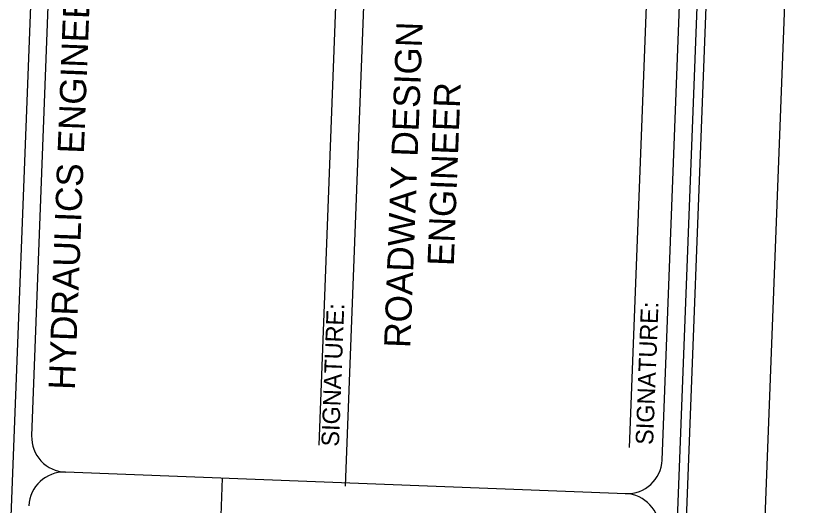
# Model space of a CAD drawing. Extents: x 2094564 to 2100382, y 679033 to 692366.
# Drawn here: x 2099233 to 2100382, y 688399 to 689098 of the extents above; entities that cross this region are included whole.
import ezdxf

# ---------------------------------------------------------------- set-up
doc = ezdxf.new("R2010")
doc.units = 0
for name, color, linetype in [('Prop Horizontal Alignment Direction Label', 7, 'Continuous'), ('Prop Horizontal Alignment Tick Label', 7, 'Continuous'), ('Prop Horizontal Alignment Tick Large', 7, 'Continuous')]:
    doc.layers.add(name, color=color, linetype=linetype)

msp = doc.modelspace()

# ---------------------------------------------------------------- linework, layer by layer
at = {"layer": 'Prop Horizontal Alignment Direction Label'}
for p, q in [((2099030, 683278.9), (2099302.1, 690373.6)), ((2099702.7, 688427.4), (2099745, 689529.9)), ((2099255.2, 688499.1), (2099293.5, 689497.2)), ((2099665, 688485.8), (2099692.6, 689206.5)), ((2100108, 688482.6), (2100135.1, 689189.6)), ((2100102.7, 688416.5), (2099303.3, 688447.2)), ((2099526.9, 688438.6), (2099468.4, 686914.7))]:
    msp.add_line(p, q, dxfattribs=at)
for points in [[(2099968.8, 682967.7), (2100252.4, 690362.2)], [(2100154.6, 688464.6), (2100192.8, 689462.7)]]:
    msp.add_lwpolyline(points, dxfattribs=at)
for centre, start, end in [((2099305, 688497.2), 177.8037, 267.8037), ((2100104.4, 688466.5), 267.8037, 357.8037), ((2099301.1, 688397.3), 87.8037, 177.8037), ((2100100.5, 688366.6), 357.8037, 87.8037)]:
    msp.add_arc(centre, 50, start, end, dxfattribs=at)
at = {"layer": 'Prop Horizontal Alignment Tick Label'}
msp.add_lwpolyline([(2099950.1, 682147.8), (2100269.5, 690474.2), (2094997.8, 690676.3), (2094678.5, 682349.9)], close=True, dxfattribs=at)
at = {"layer": 'Prop Horizontal Alignment Tick Large'}
msp.add_lwpolyline([(2094886.5, 690703.1), (2094563.9, 682289.3), (2100059.8, 682078.5), (2100382.4, 690492.3)], close=True, dxfattribs=at)

# ---------------------------------------------------------------- texts
at = {"layer": 'Prop Horizontal Alignment Direction Label'}
for s, height, p in [(' HYDRAULICS ENGINEER', 37.5, (2099316, 688550.3)), ('ROADWAY DESIGN', 37.497, (2099795.2, 688624)), ('ENGINEER', 37.5, (2099857.2, 688740.9)), ('SIGNATURE:', 25, (2100141.6, 688485.8)), ('SIGNATURE:', 25, (2099693.3, 688483.4))]:
    msp.add_text(s, height=height, rotation=87.8037, dxfattribs=at).set_placement(p)

doc.saveas('drawing.dxf')
